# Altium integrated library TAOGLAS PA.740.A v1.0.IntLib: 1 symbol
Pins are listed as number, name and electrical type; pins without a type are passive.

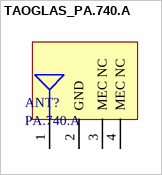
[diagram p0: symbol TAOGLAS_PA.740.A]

## TAOGLAS_PA.740.A
designator ANT?, comment PA.740.A
Warrior X Wideband Antenna for LTE & FR1 5G NR Bands (698-4900MHz); ComponentLibStatus: Created; MFG: Taoglas; Temp_High: +85C; Temp_Low: -40C
footprint TAOGLAS_PA.740.A (Warrior X Wideband Antenna for LTE & FR1 5G NR Bands (698-4900MHz))
pins: 1 RF FEED, 2 GND, 3 MEC NC, 4 MEC NC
